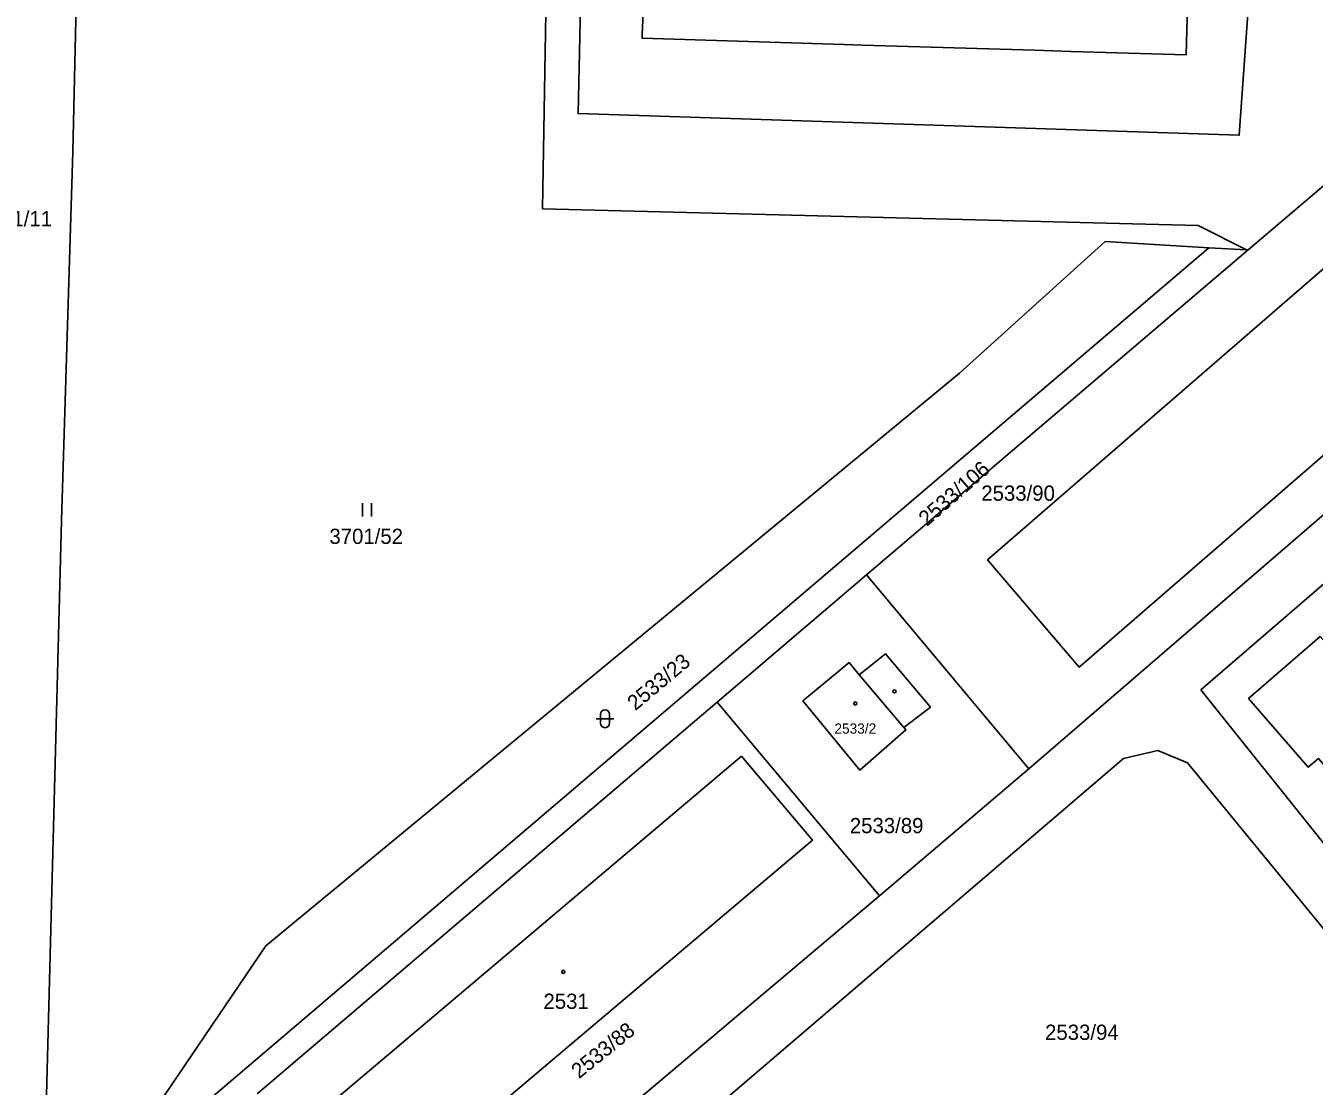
# Model space of a CAD drawing. Extents: x -527335 to -526256, y -1079142 to -1077809.
# Drawn here: x -527153.1 to -527009.3, y -1078182.2 to -1078063.8 of the extents above; entities that cross this region are included whole.
import ezdxf

# ---------------------------------------------------------------- set-up
doc = ezdxf.new("R2010")
doc.units = 0
for name, color, linetype in [('Vrstva 1', 7, 'Continuous'), ('Vrstva 2', 7, 'Continuous'), ('Vrstva 3', 7, 'Continuous'), ('Vrstva 4', 7, 'Continuous'), ('Vrstva 5', 7, 'Continuous')]:
    doc.layers.add(name, color=color, linetype=linetype)

msp = doc.modelspace()

# ---------------------------------------------------------------- linework, layer by layer
at = {"layer": 'Vrstva 1'}
for p, q in [((-527016.72, -1078088.84), (-526974.58, -1078052.94)), ((-527041.18, -1078146.78), (-526956.43, -1078073.57)), ((-527145.19, -1078194.36), (-527021.08, -1078088.59)), ((-527016.72, -1078088.84), (-527059.3, -1078125.12)), ((-527021.08, -1078088.59), (-527016.88, -1078088.83)), ((-527016.88, -1078088.83), (-527016.72, -1078088.84)), ((-527059.3, -1078125.12), (-527075.98, -1078139.33)), ((-527041.18, -1078146.78), (-527059.3, -1078125.12)), ((-527075.98, -1078139.33), (-527127.29, -1078183.04)), ((-527057.85, -1078160.95), (-527075.98, -1078139.33)), ((-527057.85, -1078160.95), (-527041.18, -1078146.78)), ((-527108.95, -1078204.05), (-527057.85, -1078160.95))]:
    msp.add_line(p, q, dxfattribs=at)
for points in [[(-527135, -1078001.05), (-527135.04, -1078002.18), (-527138.91, -1078002.31), (-527141.63, -1078004.83), (-527142.01, -1078010.14), (-527141.69, -1078010.15), (-527094.23, -1078012.01), (-527095.45, -1078084.25), (-527022.3, -1078086.11), (-527016.88, -1078088.83)], [(-527015.84, -1078035.65), (-527015.24, -1078041.58), (-527017.7, -1078076.04), (-527091.49, -1078073.63), (-527090.95, -1078049.51), (-527090.94, -1078045), (-527092.6, -1078032.05), (-527092.82, -1078025.03), (-527092.53, -1078009.03), (-527092.64, -1078007.02), (-527093.93, -1078004.22), (-527096.47, -1078002.52), (-527135, -1078001.05)], [(-527151.32, -1078203.19), (-527149.15, -1078119.04), (-527147.89, -1078077.9), (-527146.9, -1078035.16), (-527147.21, -1078003.19)], [(-527033.93, -1078026.13), (-527034.7, -1078051.14), (-527023.12, -1078051.5), (-527023.4, -1078059.92), (-527023.46, -1078061.67), (-527023.64, -1078067.07), (-527036.5, -1078066.68), (-527040.52, -1078066.56), (-527059.79, -1078065.97), (-527061.79, -1078065.91), (-527084.33, -1078065.22), (-527084.32, -1078064.79), (-527084.24, -1078062.42), (-527083.82, -1078049.59), (-527083.64, -1078049.6), (-527082.85, -1078024.68)], [(-526977.54, -1078064.26), (-527045.78, -1078123.45), (-527035.56, -1078135.42), (-526967.23, -1078076.15), (-526977.54, -1078064.26)], [(-526928.88, -1078086.88), (-526937.7, -1078076.72), (-526942.08, -1078074.31), (-526946.18, -1078074.34), (-526950.22, -1078076.11), (-527021.97, -1078137.95), (-527008.12, -1078155.27)], [(-526946.99, -1078077.23), (-527005.53, -1078127.86), (-527004.46, -1078129.1), (-527008.3, -1078132.42), (-527008.66, -1078132.01), (-527016.65, -1078138.92), (-527010, -1078146.59), (-527008.87, -1078145.61), (-527006.51, -1078148.38), (-526999.64, -1078142.45), (-526999.98, -1078142.06), (-526996.13, -1078138.73), (-526995.03, -1078140), (-526936.47, -1078089.42), (-526946.99, -1078077.23)], [(-527021.08, -1078088.59), (-527032.67, -1078087.91), (-527048.92, -1078102.61), (-527126.32, -1078166.52), (-527145.19, -1078194.36)], [(-527062.36, -1078135.83), (-527066.41, -1078139.19), (-527060.03, -1078146.92), (-527054.9, -1078142.42), (-527055.12, -1078142.16), (-527052.16, -1078139.87), (-527057.17, -1078133.94), (-527060.11, -1078136.26), (-527061.25, -1078134.91), (-527062.36, -1078135.83)], [(-526994.58, -1078193.61), (-526995.55, -1078180.16), (-527023.46, -1078146.11), (-527026.79, -1078144.7), (-527030.6, -1078145.62), (-527124.03, -1078225.56)], [(-527073.25, -1078145.36), (-527119.6, -1078184.54), (-527111.69, -1078193.91), (-527065.33, -1078154.73), (-527073.25, -1078145.36)]]:
    msp.add_lwpolyline(points, dxfattribs=at)
at = {"layer": 'Vrstva 3'}
for p, q in [((-527115.54, -1078118.61), (-527115.54, -1078117.11)), ((-527114.54, -1078118.61), (-527114.54, -1078117.11)), ((-527088.98, -1078140.67), (-527088.98, -1078141.67)), ((-527087.98, -1078141.67), (-527087.98, -1078140.67)), ((-527089.48, -1078141.17), (-527087.48, -1078141.17))]:
    msp.add_line(p, q, dxfattribs=at)
for centre, start, end in [((-527088.48, -1078140.67), 0, 180), ((-527088.48, -1078141.67), 180, 359.9879)]:
    msp.add_arc(centre, 0.5, start, end, dxfattribs=at)
at = {"layer": 'Vrstva 4'}
msp.add_line((-527060.11, -1078136.26), (-527055.12, -1078142.16), dxfattribs=at)
at = {"layer": 'Vrstva 5'}
for centre in [(-527056.18, -1078138.12), (-527060.55, -1078139.47), (-527093.14, -1078169.43)]:
    msp.add_circle(centre, 0.175, dxfattribs=at)

# ---------------------------------------------------------------- texts
at = {"layer": 'Vrstva 2'}
for s, height, p in [('3701/11', 1.7, (-527158.41, -1078086.21)), ('2533/90', 1.7, (-527046.49, -1078116.84)), ('3701/52', 1.7, (-527119.24, -1078121.66)), ('2533/2', 1.14, (-527062.88, -1078142.84)), ('2533/89', 1.7, (-527061.16, -1078153.95)), ('2531', 1.7, (-527095.35, -1078173.56)), ('2533/94', 1.7, (-527039.37, -1078177.02))]:
    msp.add_text(s, height=height, dxfattribs=at).set_placement(p)
for s, rotation, p in [('2533/106', 41, (-527052.56, -1078119.76)), ('2533/23', 40, (-527085.1, -1078140.34)), ('2533/88', 39, (-527091.38, -1078181.42))]:
    msp.add_text(s, height=1.7, rotation=rotation, dxfattribs=at).set_placement(p)

doc.saveas('drawing.dxf')
